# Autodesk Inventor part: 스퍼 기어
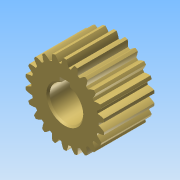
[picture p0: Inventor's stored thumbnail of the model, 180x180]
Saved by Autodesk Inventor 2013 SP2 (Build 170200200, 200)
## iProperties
Created: 2026-10
Part Number: 스퍼 기어
Material: Generic
Document SubType Name: Modeling
Designer: a
Density: 1 g/cm^3
Author: a
변환 표준: STEP AP214IS
전처리기: Build: 200, Release: 2013 SP2 Update 6 - Date: Thu 07/17/2014
전송 단위: 밀리미터
불확실성: 0.01
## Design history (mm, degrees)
node "스퍼 기어1"
body "Solid1"
node "기준1"
